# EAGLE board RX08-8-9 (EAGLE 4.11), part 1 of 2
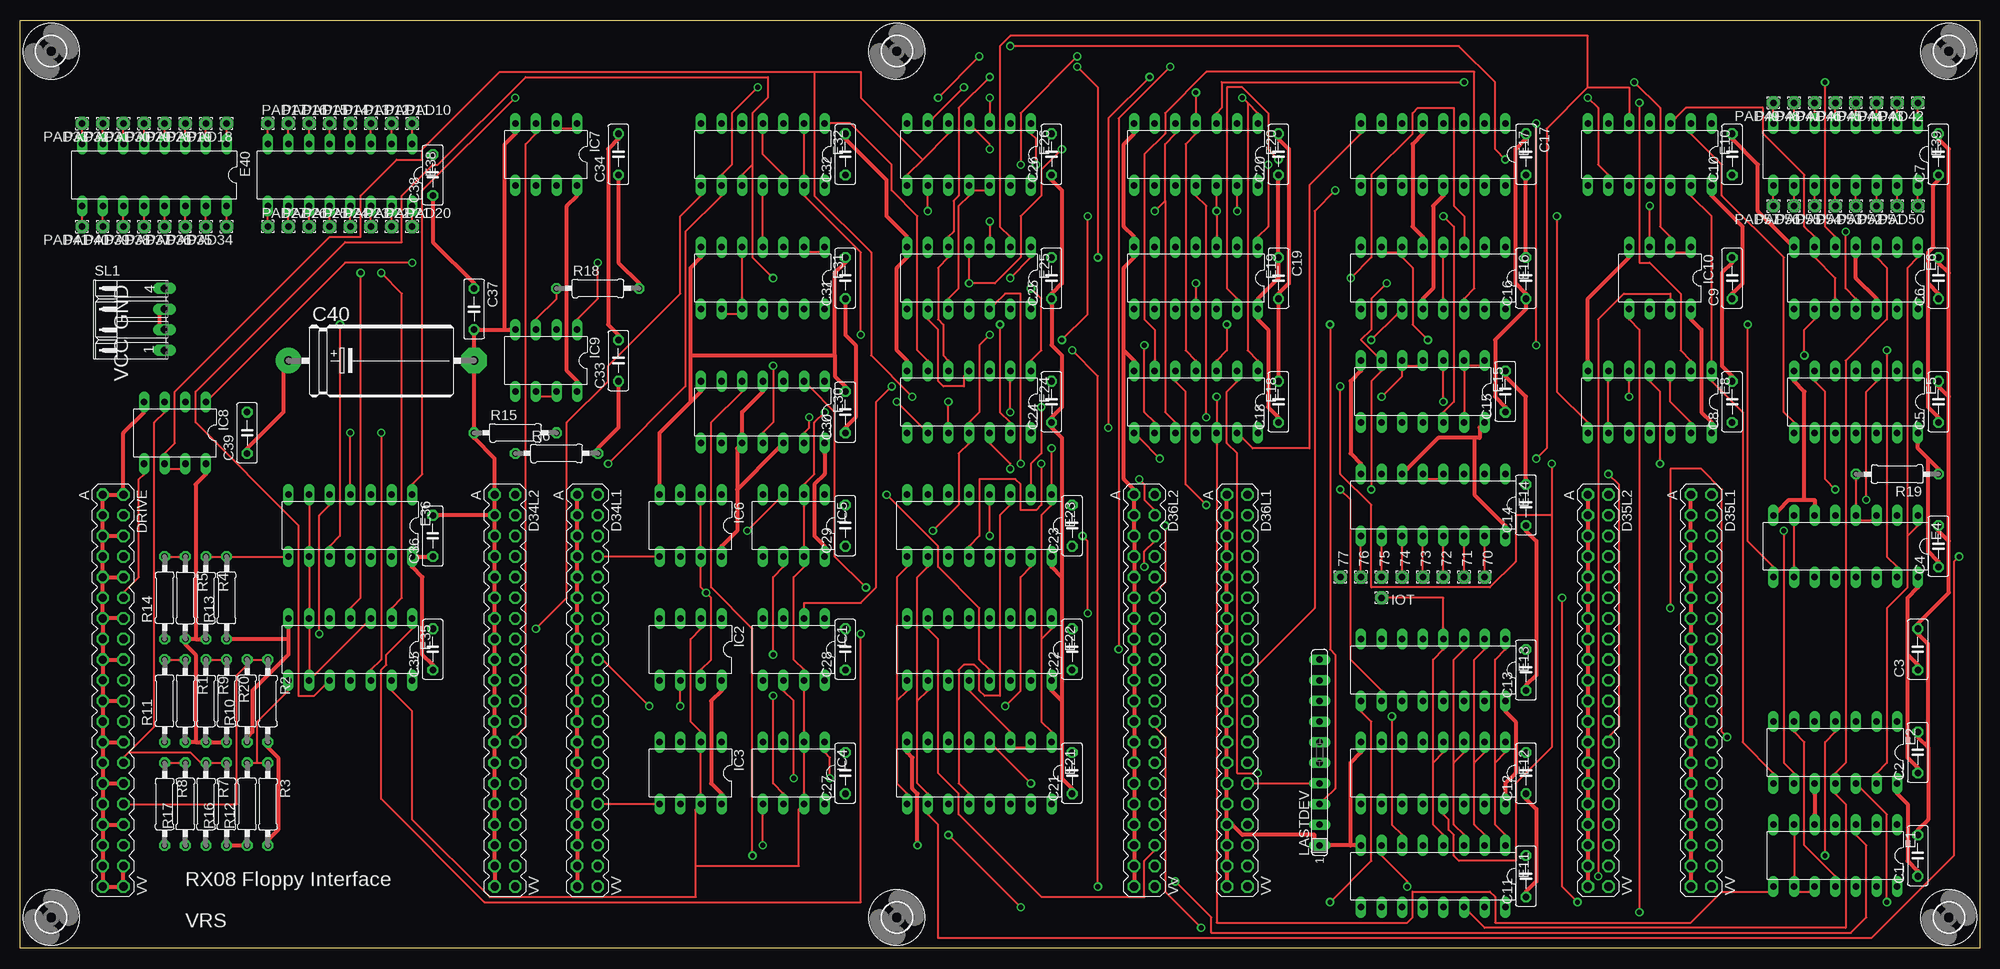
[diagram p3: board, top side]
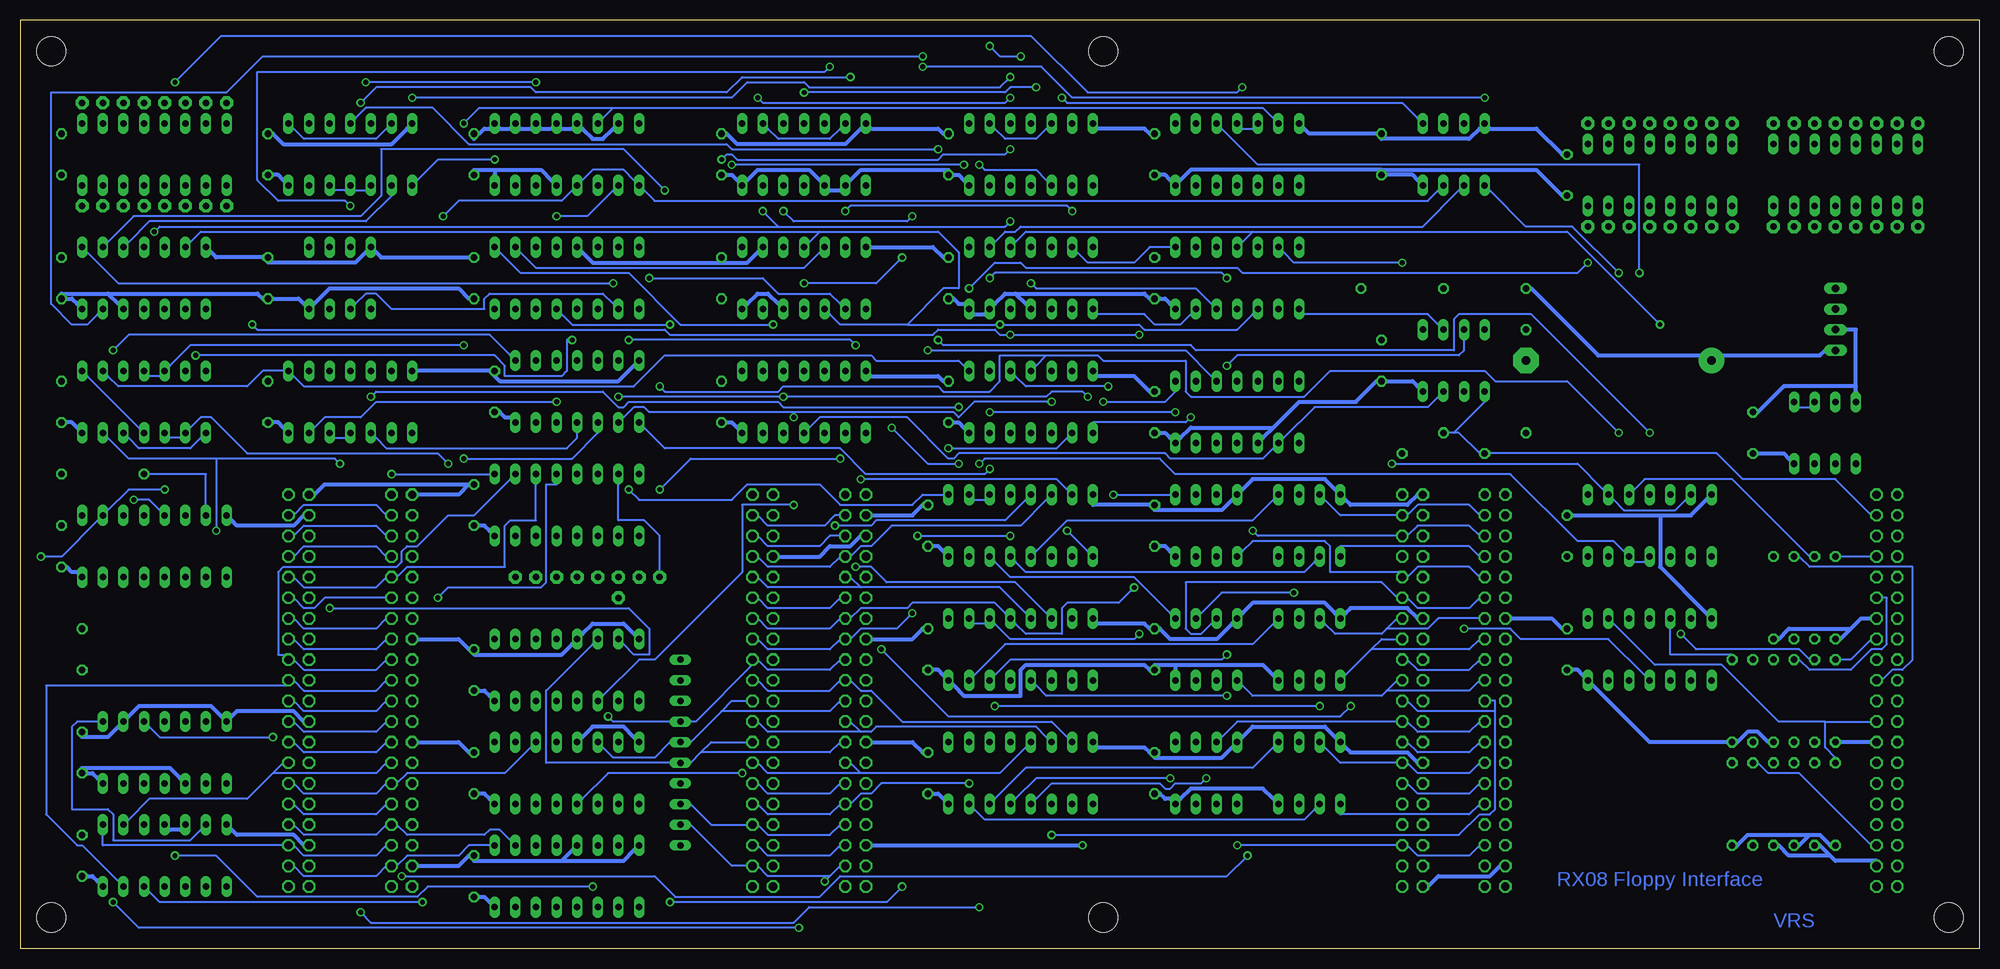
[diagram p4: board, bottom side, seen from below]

Size 241.3 x 114.3 mm. Coordinates in mm from the lower left corner, seen from the top.
Outline: 0,0 0,114.3 241.3,114.3 241.3,0 0,0
Copper layers (1*16): Top 0.035mm / dielectric 1.5mm / Bottom 0.035mm
Design rules "olimex10mil": minimum track width 10mil, minimum drill 24mil, track to track 10mil, track to pad 10mil, pad to pad 10mil, via to via 10mil, smd to smd 10mil, copper to edge 25mil, drill to drill 10mil, minimum pad ring 10mil, minimum via ring 8mil, stop-mask expansion 0mil, vias tented up to drill 0mil, thermal gap 10mil
Net classes: 1 supply: width 0.508 mm

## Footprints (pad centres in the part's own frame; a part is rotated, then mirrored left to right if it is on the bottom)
1,6/0,8 = drill 0.813 pad 1.6 octagon: 1 0,0
C050-025X075 = drill 0.813 octagon: 1 -2.54,0; 2 2.54,0
E22-9 = drill 1.016 pad 3.15 round: + -11.43,0 | drill 1.016 pad 3.15 octagon: - 11.43,0
DEC40PIN = drill 1.016 octagon: A -24.13,-1.27; AA 3.81,-1.27; B -24.13,1.27; BB 3.81,1.27; C -21.59,-1.27; CC 6.35,-1.27; D -21.59,1.27; DD 6.35,1.27; E -19.05,-1.27; EE 8.89,-1.27; F -19.05,1.27; FF 8.89,1.27; H -16.51,-1.27; HH 11.43,-1.27; J -16.51,1.27; JJ 11.43,1.27; K -13.97,-1.27; KK 13.97,-1.27; L -13.97,1.27; LL 13.97,1.27; M -11.43,-1.27; MM 16.51,-1.27; N -11.43,1.27; NN 16.51,1.27; P -8.89,-1.27; PP 19.05,-1.27; R -8.89,1.27; RR 19.05,1.27; S -6.35,-1.27; SS 21.59,-1.27; T -6.35,1.27; TT 21.59,1.27; U -3.81,-1.27; UU 24.13,-1.27; V -3.81,1.27; VV 24.13,1.27; W -1.27,-1.27; X -1.27,1.27; Y 1.27,-1.27; Z 1.27,1.27
DIL14 = drill 0.813 long: 1 -7.62,-3.81; 2 -5.08,-3.81; 3 -2.54,-3.81; 4 0,-3.81; 5 2.54,-3.81; 6 5.08,-3.81; 7 7.62,-3.81; 8 7.62,3.81; 9 5.08,3.81; 10 2.54,3.81; 11 0,3.81; 12 -2.54,3.81; 13 -5.08,3.81; 14 -7.62,3.81
DIL16 = drill 0.813 long: 1 -8.89,-3.81; 2 -6.35,-3.81; 3 -3.81,-3.81; 4 -1.27,-3.81; 5 1.27,-3.81; 6 3.81,-3.81; 7 6.35,-3.81; 8 8.89,-3.81; 9 8.89,3.81; 10 6.35,3.81; 11 3.81,3.81; 12 1.27,3.81; 13 -1.27,3.81; 14 -3.81,3.81; 15 -6.35,3.81; 16 -8.89,3.81
DIL08 = drill 0.813 long: 1 -3.81,-3.81; 2 -1.27,-3.81; 3 1.27,-3.81; 4 3.81,-3.81; 5 3.81,3.81; 6 1.27,3.81; 7 -1.27,3.81; 8 -3.81,3.81
SIL10 = drill 0.813 long: 1 -11.43,0; 2 -8.89,0; 3 -6.35,0; 4 -3.81,0; 5 -1.27,0; 6 1.27,0; 7 3.81,0; 8 6.35,0; 9 8.89,0; 10 11.43,0
0207/10 = drill 0.813 octagon: 1 -5.08,0; 2 5.08,0
04PA = drill 0.914 long: 1 -3.81,0; 2 -1.27,0; 3 1.27,0; 4 3.81,0
3,6 = hole 3.6: 0,0

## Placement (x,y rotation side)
70  [1,6/0,8]  180.34,45.72 270 top
71  [1,6/0,8]  177.8,45.72 270 top
72  [1,6/0,8]  175.26,45.72 270 top
73  [1,6/0,8]  172.72,45.72 270 top
74  [1,6/0,8]  170.18,45.72 270 top
75  [1,6/0,8]  167.64,45.72 270 top
76  [1,6/0,8]  165.1,45.72 270 top
77  [1,6/0,8]  162.56,45.72 270 top
C1  0.1  [C050-025X075]  233.68,11.43 90 top
C2  0.1  [C050-025X075]  233.68,24.13 90 top
C3  0.1  [C050-025X075]  233.68,36.83 90 top
C4  0.1  [C050-025X075]  236.22,49.53 90 top
C5  0.1  [C050-025X075]  236.22,67.31 90 top
C6  0.1  [C050-025X075]  236.22,82.55 90 top
C7  0.1  [C050-025X075]  236.22,97.79 90 top
C8  0.1  [C050-025X075]  210.82,67.31 90 top
C9  0.1  [C050-025X075]  210.82,82.55 90 top
C10  0.1  [C050-025X075]  210.82,97.79 90 top
C11  0.1  [C050-025X075]  185.42,8.89 90 top
C12  0.1  [C050-025X075]  185.42,21.59 90 top
C13  0.1  [C050-025X075]  185.42,34.29 90 top
C14  0.1  [C050-025X075]  185.42,54.61 90 top
C15  0.1  [C050-025X075]  182.88,68.58 90 top
C16  0.1  [C050-025X075]  185.42,82.55 90 top
C17  0.1  [C050-025X075]  185.42,97.79 270 top
C18  0.1  [C050-025X075]  154.94,67.31 90 top
C19  0.1  [C050-025X075]  154.94,82.55 270 top
C20  0.1  [C050-025X075]  154.94,97.79 90 top
C21  0.1  [C050-025X075]  129.54,21.59 90 top
C22  0.1  [C050-025X075]  129.54,36.83 90 top
C23  0.1  [C050-025X075]  129.54,52.07 90 top
C24  0.1  [C050-025X075]  127,67.31 90 top
C25  0.1  [C050-025X075]  127,82.55 90 top
C26  0.1  [C050-025X075]  127,97.79 90 top
C27  0.1  [C050-025X075]  101.6,21.59 90 top
C28  0.1  [C050-025X075]  101.6,36.83 90 top
C29  0.1  [C050-025X075]  101.6,52.07 90 top
C30  0.1  [C050-025X075]  101.6,66.04 90 top
C31  0.1  [C050-025X075]  101.6,82.55 90 top
C32  0.1  [C050-025X075]  101.6,97.79 90 top
C33  0.1  [C050-025X075]  73.66,72.39 90 top
C34  0.1  [C050-025X075]  73.66,97.79 90 top
C35  0.1  [C050-025X075]  50.8,36.83 90 top
C36  0.1  [C050-025X075]  50.8,50.8 90 top
C37  0.1  [C050-025X075]  55.88,78.74 270 top
C38  0.1  [C050-025X075]  50.8,95.25 90 top
C39  0.1  [C050-025X075]  27.94,63.5 90 top
C40  100uf  [E22-9]  44.45,72.39 0 top
D34L1  [DEC40PIN]  69.85,31.75 270 top
D34L2  [DEC40PIN]  59.69,31.75 270 top
D35L1  [DEC40PIN]  207.01,31.75 270 top
D35L2  [DEC40PIN]  194.31,31.75 270 top
D36L1  [DEC40PIN]  149.86,31.75 270 top
D36L2  [DEC40PIN]  138.43,31.75 270 top
DRIVE  [DEC40PIN]  11.43,31.75 270 top
E1  74LS10N  [DIL14]  223.52,11.43 180 top
E2  74LS74N  [DIL14]  223.52,24.13 180 top
E4  74LS161N  [DIL16]  224.79,49.53 180 top
E5  74LS00N  [DIL14]  226.06,67.31 180 top
E6  74LS74N  [DIL14]  226.06,82.55 180 top
E8  74LS10N  [DIL14]  200.66,67.31 180 top
E10  74LS10N  [DIL14]  200.66,97.79 180 top
E11  74LS138N  [DIL16]  173.99,8.89 180 top
E12  74LS138N  [DIL16]  173.99,21.59 180 top
E13  74LS138N  [DIL16]  173.99,34.29 180 top
E14  74LS138N  [DIL16]  173.99,54.61 180 top
E15  74LS00N  [DIL14]  172.72,68.58 180 top
E16  74LS75N  [DIL16]  173.99,82.55 180 top
E17  74LS76N  [DIL16]  173.99,97.79 180 top
E18  74LS02N  [DIL14]  144.78,67.31 180 top
E19  74LS74N  [DIL14]  144.78,82.55 180 top
E20  74HCT32N  [DIL14]  144.78,97.79 180 top
E21  74LS195N  [DIL16]  118.11,21.59 180 top
E22  74LS195N  [DIL16]  118.11,36.83 180 top
E23  74LS195N  [DIL16]  118.11,52.07 180 top
E24  74LS08N  [DIL14]  116.84,67.31 180 top
E25  74LS04N  [DIL14]  116.84,82.55 180 top
E26  74LS02N  [DIL14]  116.84,97.79 180 top
E30  74LS74N  [DIL14]  91.44,66.04 180 top
E31  74LS20N  [DIL14]  91.44,82.55 180 top
E32  74LS27N  [DIL14]  91.44,97.79 180 top
E35  74HCT02N  [DIL14]  40.64,36.83 180 top
E36  74HCT02N  [DIL14]  40.64,52.07 180 top
E38  SPARE  [DIL16]  39.37,95.25 180 top
E39  SPARE  [DIL16]  224.79,97.79 180 top
E40  SPARE  [DIL16]  16.51,95.25 180 top
IC1  DS75452N  [DIL08]  95.25,36.83 180 top
IC2  DS75452N  [DIL08]  82.55,36.83 180 top
IC3  DS75452N  [DIL08]  82.55,21.59 180 top
IC4  DS75452N  [DIL08]  95.25,21.59 180 top
IC5  DS75452N  [DIL08]  95.25,52.07 180 top
IC6  DS75452N  [DIL08]  82.55,52.07 180 top
IC7  DS75452N  [DIL08]  64.77,97.79 180 top
IC8  DS75452N  [DIL08]  19.05,63.5 180 top
IC9  DS75452N  [DIL08]  64.77,72.39 180 top
IC10  DS75452N  [DIL08]  201.93,82.55 180 top
IOT  [1,6/0,8]  167.64,43.18 270 top
LASTDEV  100  [SIL10]  160.02,24.13 90 top
PAD10  [1,6/0,8]  48.26,101.6 0 top
PAD11  [1,6/0,8]  45.72,101.6 0 top
PAD12  [1,6/0,8]  43.18,101.6 0 top
PAD13  [1,6/0,8]  40.64,101.6 0 top
PAD14  [1,6/0,8]  38.1,101.6 0 top
PAD15  [1,6/0,8]  35.56,101.6 0 top
PAD16  [1,6/0,8]  33.02,101.6 0 top
PAD17  [1,6/0,8]  30.48,101.6 0 top
PAD18  [1,6/0,8]  25.4,101.6 180 top
PAD19  [1,6/0,8]  22.86,101.6 180 top
PAD20  [1,6/0,8]  48.26,88.9 0 top
PAD21  [1,6/0,8]  45.72,88.9 0 top
PAD22  [1,6/0,8]  43.18,88.9 0 top
PAD23  [1,6/0,8]  40.64,88.9 0 top
PAD24  [1,6/0,8]  38.1,88.9 0 top
PAD25  [1,6/0,8]  35.56,88.9 0 top
PAD26  [1,6/0,8]  33.02,88.9 0 top
PAD27  [1,6/0,8]  30.48,88.9 0 top
PAD28  [1,6/0,8]  20.32,101.6 180 top
PAD29  [1,6/0,8]  17.78,101.6 180 top
PAD30  [1,6/0,8]  15.24,101.6 180 top
PAD31  [1,6/0,8]  12.7,101.6 180 top
PAD32  [1,6/0,8]  10.16,101.6 180 top
PAD33  [1,6/0,8]  7.62,101.6 180 top
PAD34  [1,6/0,8]  25.4,88.9 180 top
PAD35  [1,6/0,8]  22.86,88.9 180 top
PAD36  [1,6/0,8]  20.32,88.9 180 top
PAD37  [1,6/0,8]  17.78,88.9 180 top
PAD38  [1,6/0,8]  15.24,88.9 180 top
PAD39  [1,6/0,8]  12.7,88.9 180 top
PAD40  [1,6/0,8]  10.16,88.9 180 top
PAD41  [1,6/0,8]  7.62,88.9 180 top
PAD42  [1,6/0,8]  233.68,104.14 180 top
PAD43  [1,6/0,8]  231.14,104.14 180 top
PAD44  [1,6/0,8]  228.6,104.14 180 top
PAD45  [1,6/0,8]  226.06,104.14 180 top
PAD46  [1,6/0,8]  223.52,104.14 180 top
PAD47  [1,6/0,8]  220.98,104.14 180 top
PAD48  [1,6/0,8]  218.44,104.14 180 top
PAD49  [1,6/0,8]  215.9,104.14 180 top
PAD50  [1,6/0,8]  233.68,91.44 180 top
PAD51  [1,6/0,8]  231.14,91.44 180 top
PAD52  [1,6/0,8]  228.6,91.44 180 top
PAD53  [1,6/0,8]  226.06,91.44 180 top
PAD54  [1,6/0,8]  223.52,91.44 180 top
PAD55  [1,6/0,8]  220.98,91.44 180 top
PAD56  [1,6/0,8]  218.44,91.44 180 top
PAD57  [1,6/0,8]  215.9,91.44 180 top
R1  180  [0207/10]  20.32,30.48 270 top
R2  180  [0207/10]  30.48,30.48 270 top
R3  180  [0207/10]  30.48,17.78 270 top
R4  180  [0207/10]  22.86,43.18 270 top
R5  180  [0207/10]  20.32,43.18 270 top
R6  180  [0207/10]  66.04,60.96 0 top
R7  180  [0207/10]  22.86,17.78 270 top
R8  180  [0207/10]  17.78,17.78 270 top
R9  390  [0207/10]  22.86,30.48 270 top
R10  390  [0207/10]  27.94,30.48 90 top
R11  390  [0207/10]  17.78,30.48 90 top
R12  390  [0207/10]  27.94,17.78 90 top
R13  390  [0207/10]  25.4,43.18 90 top
R14  390  [0207/10]  17.78,43.18 90 top
R15  390  [0207/10]  60.96,63.5 0 top
R16  390  [0207/10]  25.4,17.78 90 top
R17  390  [0207/10]  20.32,17.78 90 top
R18  10K  [0207/10]  71.12,81.28 0 top
R19  10K  [0207/10]  231.14,58.42 180 top
R20  180  [0207/10]  25.4,30.48 270 top
SL1  [04PA]  17.78,77.47 90 top
U$1  [3,6]  237.49,3.81 0 top
U$2  [3,6]  237.49,110.49 0 top
U$3  [3,6]  3.81,110.49 0 top
U$4  [3,6]  3.81,3.81 0 top
U$5  [3,6]  107.95,110.49 0 top
U$6  [3,6]  107.95,3.81 0 top

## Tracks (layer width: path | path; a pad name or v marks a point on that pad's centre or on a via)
8/12  (via drill 0.61)
  Top 0.254: v201.93,59.69 201.93,68.58 200.66,69.85 E8.4 | v217.17,51.44 217.17,22.86 218.44,21.59 E2.9
  Bottom 0.254: v201.93,59.69 202.56,60.33 217.17,60.33 | 217.17,60.33 227.97,60.33 230.5,62.87 E5.13 | 217.17,60.33 v217.17,51.44
8/12\  (via drill 0.61)
  Top 0.254: E2.8 215.9,21.59 212.09,25.4 212.09,66.04 208.28,69.85 E8.1 208.28,72.39 208.28,90.17 205.74,92.71 E10.13 | v48.26,84.45 40.01,84.45 23.5,67.94 IC8.1 | v124.46,81.28 125.73,80.01 125.73,73.66 124.46,72.39 E24.1
  Bottom 0.254: IC8.2 20.95,66.67 22.23,66.67 IC8.1 | E24.1 125.09,71.75 125.73,72.39 135.89,72.39 136.53,73.03 161.93,73.03 165.74,69.22 206.38,69.22 207.65,70.48 E8.1 208.91,71.12 211.46,71.12 213.36,69.22 229.24,69.22 230.5,70.48 E5.2 | v48.26,84.45 49.53,83.19 90.81,83.19 91.44,83.82 117.47,83.82 118.11,84.45 121.28,84.45 v124.46,81.28
ACB00\
  Bottom 0.254: IC6.3 80.64,55.24 78.74,53.34 71.75,53.34 D34L1.D 70.48,53.34 69.22,54.61 62.87,54.61 61.59,53.34 D34L2.D
ACB01\
  Top 0.254: IC6.5 78.11,48.26 71.75,48.26 D34L1.J
  Bottom 0.254: D34L2.J 61.59,48.26 62.87,49.53 78.74,49.53 IC6.5
ACB02\
  Bottom 0.254: IC1.3 94.61,40.01 95.89,38.73 97.16,38.73 97.79,39.37 97.79,45.09 73.66,45.09 71.75,43.18 D34L1.N 70.48,43.18 69.22,41.91 62.87,41.91 61.59,43.18 D34L2.N
ACB03\
  Bottom 0.254: 74.93,36.83 73.66,38.1 71.75,38.1 D34L1.T | 74.93,36.83 78.11,33.66 IC2.5 | 74.93,36.83 62.87,36.83 61.59,38.1 D34L2.T
ACB04\
  Bottom 0.254: 73.03,31.75 71.75,33.02 D34L1.X | 73.03,31.75 73.66,31.11 89.53,31.11 90.81,32.38 IC1.5 | 73.03,31.75 62.87,31.75 61.59,33.02 D34L2.X
ACB05\
  Bottom 0.254: IC4.3 93.34,26.04 91.44,27.94 71.75,27.94 D34L1.BB 70.48,27.94 69.22,26.67 62.87,26.67 61.59,27.94 D34L2.BB
ACB06\
  Bottom 0.254: IC3.3 80.64,24.77 78.74,22.86 71.75,22.86 D34L1.FF 70.48,22.86 69.22,21.59 62.87,21.59 61.59,22.86 D34L2.FF
ACB07\
  Top 0.254: IC3.5 78.11,17.78 71.75,17.78 D34L1.LL
  Bottom 0.254: D34L2.LL 61.59,17.78 62.87,16.51 78.74,16.51 IC3.5
ACB08\  (via drill 0.61)
  Top 0.254: v91.44,12.7 91.44,16.51 IC4.5
  Bottom 0.254: v91.44,12.7 71.75,12.7 D34L1.RR 70.48,12.7 69.22,11.43 62.87,11.43 61.59,12.7 D34L2.RR
ACB09\  (via drill 0.61)
  Top 0.254: v89.53,51.44 93.34,55.24 IC5.3
  Bottom 0.254: v89.53,51.44 88.9,50.8 71.75,50.8 D34L1.F 70.48,50.8 69.22,52.07 62.87,52.07 61.59,50.8 D34L2.F
ACB10\
  Bottom 0.254: IC5.5 90.81,48.9 89.53,50.16 80.64,50.16 80.01,49.53 80.01,46.35 71.12,46.35 D34L1.L 70.48,45.72 69.22,46.99 62.87,46.99 61.59,45.72 D34L2.L
ACB11\
  Bottom 0.254: 73.03,39.37 71.75,40.64 D34L1.R | 73.03,39.37 73.66,38.73 79.38,38.73 80.64,40.01 IC2.3 | 73.03,39.37 67.94,39.37 66.67,40.64 61.59,40.64 D34L2.R
ACCLEAR\
  Top 0.254: IC7.3 63.5,100.33 62.23,99.06 62.23,27.3 60.96,26.04 D34L2.DD
  Bottom 0.254: D34L1.DD 70.48,25.4 69.22,24.13 62.87,24.13 61.59,25.4 D34L2.DD
BAC00  (via drill 0.61)
  Top 0.254: v137.79,57.78 138.43,57.15 138.43,55.24 139.7,53.98 D36L2.D
  Bottom 0.254: v137.79,57.78 113.67,57.78 112.39,56.52 E23.7 | D36L1.D 150.5,53.34 149.22,52.07 142.24,52.07 140.97,53.34 140.34,53.34 D36L2.D
BAC01
  Bottom 0.254: E23.6 114.94,55.24 118.11,52.07 133.99,52.07 136.53,49.53 137.79,49.53 139.06,48.26 D36L2.J 140.34,48.26 141.6,46.99 149.22,46.99 150.5,48.26 D36L1.J
BAC02  (via drill 0.61)
  Top 0.254: v140.97,52.07 140.97,45.09 139.7,43.81 D36L2.N
  Bottom 0.254: v140.97,52.07 136.53,52.07 135.89,52.7 120.02,52.7 117.47,55.24 E23.5 | D36L1.N 150.5,43.18 149.22,41.91 141.6,41.91 140.34,43.18 D36L2.N
BAC03  (via drill 0.61)
  Top 0.254: v119.38,50.8 119.38,54.61 E23.4 | v130.81,50.8 131.44,50.16 v131.44,41.27
  Bottom 0.254: v130.81,50.8 v119.38,50.8 | v131.44,41.27 133.35,39.37 137.79,39.37 139.06,38.1 D36L2.T 140.34,38.1 141.6,36.83 149.22,36.83 150.5,38.1 D36L1.T
BAC04  (via drill 0.61)
  Top 0.254: v161.93,93.34 159.38,90.81 159.38,41.91 151.13,33.66 D36L1.X
  Bottom 0.254: E21.7 112.39,26.04 114.3,27.94 132.72,27.94 136.53,31.75 137.79,31.75 139.06,33.02 D36L2.X 140.34,33.02 141.6,31.75 149.22,31.75 150.5,33.02 D36L1.X | v161.93,93.34 167,98.42 196.85,98.42 196.85,92.71 199.39,90.17 227.33,90.17 230.5,87 E6.2
BAC05  (via drill 0.61)
  Top 0.254: v229.87,5.71 229.87,16.51 226.69,19.68 E2.12 | v145.41,2.54 140.97,6.99 140.97,26.04 139.7,27.3 D36L2.BB
  Bottom 0.254: 137.79,26.67 136.53,26.67 135.89,27.3 116.2,27.3 114.94,26.04 E21.6 | 137.79,26.67 139.06,27.94 D36L2.BB | v229.87,5.71 226.69,2.54 v145.41,2.54 | 137.79,26.67 149.22,26.67 150.5,27.94 D36L1.BB
BAC06
  Bottom 0.254: 137.79,21.59 120.65,21.59 117.47,24.77 E21.5 | 137.79,21.59 139.06,22.86 D36L2.FF | 137.79,21.59 149.22,21.59 150.5,22.86 D36L1.FF
BAC07  (via drill 0.61)
  Top 0.254: v124.46,20.32 120.02,24.77 E21.4
  Bottom 0.254: v124.46,20.32 135.25,20.32 136.53,19.05 137.79,19.05 139.06,17.78 D36L2.LL 140.34,17.78 141.6,16.51 149.22,16.51 150.5,17.78 D36L1.LL
BAC08
  Top 0.254: E22.7 111.76,39.37 113.03,38.1 113.03,21.59 115.57,19.05 115.57,16.51 125.73,6.35 138.43,6.35 138.43,10.79 139.7,12.06 D36L2.RR
  Bottom 0.254: D36L1.RR 150.5,12.7 149.22,11.43 141.6,11.43 140.34,12.7 D36L2.RR
BAC09  (via drill 0.61)
  Top 0.254: v138.43,46.99 138.43,48.9 139.7,50.16 D36L2.F
  Bottom 0.254: v138.43,46.99 136.53,46.99 134.62,45.09 118.75,45.09 114.94,41.27 E22.6 | D36L1.F 150.5,50.8 149.22,49.53 142.88,49.53 141.6,50.8 140.34,50.8 D36L2.F
BAC10
  Bottom 0.254: 137.79,44.45 120.65,44.45 117.47,41.27 E22.5 | 137.79,44.45 139.06,45.72 D36L2.L | 137.79,44.45 149.22,44.45 150.5,45.72 D36L1.L
BAC11  (via drill 0.61)
  Top 0.254: v104.14,44.45 100.33,48.26 100.33,66.04 97.16,69.22 E30.2
  Bottom 0.254: D36L1.R 150.5,40.64 149.22,39.37 141.6,39.37 140.34,40.64 D36L2.R 139.06,40.64 137.79,41.91 132.08,41.91 131.44,42.55 121.28,42.55 120.02,41.27 E22.4 118.75,40.01 117.47,38.73 113.03,38.73 113.03,41.91 112.39,42.55 106.05,42.55 v104.14,44.45
BINIT  (via drill 0.61)
  Top 0.254: v142.24,8.26 146.69,3.81 146.69,1.91 225.43,1.91 227.33,3.81 227.33,12.7 226.06,13.97 E1.3
  Bottom 0.254: LASTDEV.2 158.75,15.24 153.67,10.16 151.76,10.16 D36L1.TT 150.5,10.16 149.22,8.89 141.6,8.89 | 141.6,8.89 140.34,10.16 D36L2.TT | v142.24,8.26 141.6,8.89
BIOP1  (via drill 0.61)
  Top 0.254: v168.91,28.57 168.91,15.24 170.18,13.97 E11.6
  Bottom 0.254: D36L2.V 140.34,35.56 141.6,34.29 149.22,34.29 150.5,35.56 D36L1.V 151.13,34.92 158.12,27.94 158.75,27.94 LASTDEV.7 161.29,27.94 168.28,27.94 v168.91,28.57
BIOP2
  Bottom 0.254: 154.94,29.21 153.67,30.48 151.76,30.48 D36L1.Z | 154.94,29.21 158.75,25.4 LASTDEV.6 161.29,25.4 163.19,23.5 168.28,23.5 169.54,24.77 E12.6 | 154.94,29.21 141.6,29.21 140.34,30.48 D36L2.Z
BIOP4
  Bottom 0.254: 157.48,24.13 156.21,25.4 151.76,25.4 D36L1.DD | 157.48,24.13 158.75,22.86 LASTDEV.5 161.29,22.86 176.53,22.86 176.53,31.75 170.81,37.47 E13.6 | 157.48,24.13 141.6,24.13 140.34,25.4 D36L2.DD
BMB00
  Bottom 0.254: D35L2.D 196.22,53.34 197.49,54.61 206.38,54.61 207.65,53.34 D35L1.D
BMB01
  Bottom 0.254: D35L2.J 196.22,48.26 197.49,49.53 206.38,49.53 207.65,48.26 D35L1.J
BMB02
  Bottom 0.254: D35L2.N 196.22,43.18 203.84,43.18 205.1,41.91 206.38,41.91 207.65,43.18 D35L1.N
BMB03
  Bottom 0.254: E1.13 229.24,8.26 233.68,12.7 234.31,12.7 238.12,16.51 238.12,32.38 208.28,32.38 D35L1.X 207.65,33.02 206.38,31.75 197.49,31.75 196.22,33.02 D35L2.X
BMB03\
  Bottom 0.254: D35L2.T 196.22,38.1 197.49,36.83 206.38,36.83 207.65,38.1 D35L1.T
BMB04
  Bottom 0.254: 210.19,21.59 208.91,22.86 D35L1.FF | 210.19,21.59 213.36,18.41 225.43,18.41 227.97,15.88 E1.2 | 210.19,21.59 197.49,21.59 196.22,22.86 D35L2.FF
BMB04\
  Bottom 0.254: D35L2.BB 196.22,27.94 197.49,26.67 206.38,26.67 207.65,27.94 D35L1.BB
BMB05
  Bottom 0.254: E1.1 231.14,13.97 231.14,12.7 208.91,12.7 D35L1.RR 207.65,12.7 206.38,11.43 197.49,11.43 196.22,12.7 D35L2.RR
BMB05\
  Bottom 0.254: D35L2.LL 196.22,17.78 197.49,16.51 206.38,16.51 207.65,17.78 D35L1.LL
BMB06
  Bottom 0.254: E14.3 177.8,57.15 177.8,52.7 180.97,52.7 181.61,52.07 181.61,46.99 193.68,46.99 194.94,45.72 D35L2.L 196.22,45.72 197.49,44.45 206.38,44.45 207.65,45.72 D35L1.L
BMB06\
  Bottom 0.254: D35L2.F 196.22,50.8 197.49,52.07 206.38,52.07 207.65,50.8 D35L1.F
BMB07
  Bottom 0.254: E14.2 180.97,57.78 185.42,53.34 188.59,53.34 192.41,49.53 193.68,49.53 194.31,48.9 194.31,47.62 194.94,46.99 208.91,46.99 209.55,46.35 209.55,36.2 208.28,36.2 D35L1.V 207.65,35.56 206.38,34.29 197.49,34.29 196.22,35.56 D35L2.V
BMB07\
  Bottom 0.254: D35L2.R 196.22,40.64 197.49,39.37 206.38,39.37 207.65,40.64 D35L1.R
BMB08  (via drill 0.61)
  Top 0.254: v195.58,58.42 196.85,57.15 196.85,27.3 195.58,26.04 D35L2.DD
  Bottom 0.254: v195.58,58.42 183.51,58.42 E14.1 | D35L1.DD 207.65,25.4 206.38,24.13 197.49,24.13 196.22,25.4 D35L2.DD
BMB08\
  Bottom 0.254: D35L2.Z 196.22,30.48 197.49,29.21 206.38,29.21 207.65,30.48 D35L1.Z
BMB09
  Top 0.254: 176.53,22.86 176.53,15.24 177.8,13.97 E11.3 | 176.53,22.86 177.8,24.13 E12.3 | 176.53,22.86 176.53,35.56 177.8,36.83 E13.3
  Bottom 0.254: D35L1.JJ 207.65,20.32 206.38,19.05 197.49,19.05 196.22,20.32 D35L2.JJ 194.94,20.32 193.68,21.59 181.61,21.59 178.44,24.77 E12.3
BMB10
  Top 0.254: 179.07,22.86 179.07,15.24 180.34,13.97 E11.2 | 179.07,22.86 180.34,24.13 E12.2 | 179.07,22.86 179.07,35.56 180.34,36.83 E13.2
  Bottom 0.254: D35L1.NN 207.65,15.24 206.38,13.97 197.49,13.97 196.22,15.24 D35L2.NN 194.94,15.24 193.68,13.97 184.15,13.97 183.51,14.61 182.25,14.61 180.97,13.34 E11.2
BMB11
  Top 0.254: 181.61,22.86 181.61,15.24 182.88,13.97 E11.1 | 181.61,22.86 182.88,24.13 E12.1 | 181.61,22.86 181.61,35.56 182.88,36.83 E13.1
  Bottom 0.254: D35L1.TT 207.65,10.16 206.38,8.89 197.49,8.89 196.22,10.16 D35L2.TT 194.94,10.16 193.68,11.43 187.32,11.43 186.06,12.7 183.51,12.7 E11.1
BRUN\
  Bottom 0.254: D34L2.JJ 61.59,20.32 62.87,19.05 69.22,19.05 70.48,20.32 D34L1.JJ
BTS1  (via drill 0.61)
  Top 0.254: E16.13 175.26,80.01 175.26,85.09 E16.4 | v161.29,76.83 161.29,36.83 161.93,36.2 161.93,19.68 160.66,18.41 LASTDEV.3
  Bottom 0.254: LASTDEV.3 158.75,17.78 156.21,15.24 151.76,15.24 D36L1.NN 150.5,15.24 149.22,13.97 141.6,13.97 140.34,15.24 D36L2.NN | v161.29,76.83 173.35,76.83 174.62,78.11 E16.13
BTS3
  Top 0.254: LASTDEV.4 158.75,20.32 151.76,20.32 D36L1.JJ
  Bottom 0.254: D36L2.JJ 140.34,20.32 141.6,19.05 149.22,19.05 150.5,20.32 D36L1.JJ
CLK_BUF  (via drill 0.61)
  Top 0.254: v223.52,56.52 222.25,57.78 222.25,68.58 220.98,69.85 E5.6 | 110.49,30.48 110.49,20.32 111.76,19.05 E21.10 111.76,16.51 113.03,15.24 113.03,1.27 227.97,1.27 238.12,11.43 238.12,47.62 v238.76,48.26 | 110.49,30.48 111.76,31.75 E22.10 | 110.49,30.48 110.49,45.72 111.76,46.99 E23.10
  Bottom 0.254: v223.52,56.52 227.97,56.52 230.5,53.98 E4.2 231.78,52.7 236.22,48.26 v238.76,48.26
CLK_PARITY\  (via drill 0.61)
  Top 0.254: v186.69,74.3 v186.69,101.6
  Bottom 0.254: E5.4 225.43,70.48 224.16,70.48 E5.5 222.88,71.75 220.34,74.3 v186.69,74.3 | 168.28,103.5 88.27,103.5 87,102.23 E32.6 | 168.28,103.5 169.54,102.23 E17.6 | v186.69,101.6 184.78,103.5 168.28,103.5
DONE  (via drill 0.61)
  Top 0.254: v39.37,76.83 39.37,50.8 38.1,49.53 E36.10 | E32.11 91.44,92.71 91.44,87.63 E31.4 | v149.86,90.81 149.86,92.71 E20.13 | v119.38,89.53 119.38,87.63 E25.3 | v224.79,88.27 224.79,81.28 226.06,80.01 E6.11
  Bottom 0.254: v39.37,76.83 50.8,88.27 89.53,88.27 | 89.53,88.27 90.81,87 E31.4 | 89.53,88.27 117.47,88.27 118.75,87 E25.3 | 147.96,88.9 v149.86,90.81 | 147.96,88.9 120.02,88.9 v119.38,89.53 | v224.79,88.27 224.16,88.9 147.96,88.9
DONE\  (via drill 0.61)
  Top 0.254: E25.4 116.84,85.09 v116.84,81.92 120.02,81.92 123.19,85.09 123.19,90.17 125.73,92.71 125.73,95.89 v128.27,98.42
  Bottom 0.254: v116.84,81.92 116.2,81.28 96.52,81.28 94.61,79.38 E31.12 | v128.27,98.42 153.67,98.42 154.31,99.06 186.06,99.06 190.5,103.5 198.75,103.5 200.03,102.23 E10.4
DONE_FF
  Bottom 0.254: E16.10 168.28,79.38 169.54,80.64 183.51,80.64 184.15,80.01 184.15,78.74 195.58,78.74 197.49,80.64 198.75,80.64 200.03,79.38 IC10.6
DONE_SKIP  (via drill 0.61)
  Top 0.254: v111.76,90.81 111.76,92.71 E26.9 | v139.7,90.81 140.97,92.08 | 140.97,92.08 140.97,99.06 142.24,100.33 E20.5 | 140.97,92.08 140.97,66.04 142.24,64.77 E18.10
  Bottom 0.254: v111.76,90.81 112.39,91.44 139.06,91.44 v139.7,90.81
ENB_BUF_LD\  (via drill 0.61)
  Top 0.254: 107.95,30.48 107.95,20.32 109.22,19.05 E21.9 | 107.95,30.48 109.22,31.75 E22.9 | 107.95,30.48 107.95,45.72 109.22,46.99 E23.9 | E32.2 96.52,100.33 96.52,95.25 E32.13 96.52,92.71 103.5,85.72 v103.5,75.56 | v212.72,76.83 212.72,50.16 215.9,46.99 E4.9 | v119.38,75.56 118.11,74.3 118.11,66.04 116.84,64.77 E24.11 116.84,62.23 115.57,60.96 115.57,54.61 v112.39,51.44
  Bottom 0.254: v212.72,76.83 212.09,76.2 161.93,76.2 161.29,75.56 128.91,75.56 128.27,76.2 121.28,76.2 120.65,75.56 v119.38,75.56 v103.5,75.56 | v112.39,51.44 109.86,48.9 E23.9
ERR_SKIP  (via drill 0.61)
  Top 0.254: v116.2,106.05 112.39,102.23 E26.6 | v144.78,105.41 144.78,102.87 E20.4 144.78,100.33 143.51,99.06 143.51,73.66 144.78,72.39 E18.4
  Bottom 0.254: v116.2,106.05 119.38,106.05 120.02,105.41 v144.78,105.41
ERROR  (via drill 0.61)
  Top 0.254: v60.96,104.78 49.53,93.34 49.53,58.42 48.26,57.15 E36.1 | v130.18,108.58 132.72,106.05 v132.72,85.09 | v144.78,81.92 144.78,80.01 E19.11
  Bottom 0.254: v60.96,104.78 111.76,104.78 115.57,108.58 v130.18,108.58 | v132.72,85.09 135.89,81.92 v144.78,81.92
GND  (via drill 0.61)
  Top 0.508: D34L1.UU 68.58,8.26 68.58,9.53 D34L1.SS 68.58,10.79 68.58,12.06 D34L1.PP 68.58,13.34 68.58,14.61 D34L1.MM 68.58,15.88 68.58,17.14 D34L1.KK 68.58,18.41 68.58,19.68 D34L1.HH 68.58,20.95 68.58,22.23 D34L1.EE 68.58,23.5 68.58,24.77 D34L1.CC 68.58,26.04 68.58,27.3 D34L1.AA 68.58,28.57 68.58,29.84 D34L1.Y 68.58,31.11 68.58,32.38 D34L1.W 68.58,33.66 68.58,34.92 D34L1.U 68.58,36.2 68.58,37.47 D34L1.S 68.58,38.73 68.58,40.01 D34L1.P 68.58,41.27 68.58,42.55 D34L1.M 68.58,43.81 68.58,45.09 D34L1.K 68.58,46.35 68.58,47.62 D34L1.H 68.58,48.9 68.58,50.16 D34L1.E 68.58,51.44 68.58,52.7 D34L1.C 68.58,53.98 68.58,55.24 D34L1.A | 100.33,73.03 100.33,70.48 101.6,69.22 C30.2 | 100.33,73.03 100.33,83.19 101.6,84.45 C31.2 | E24.7 109.22,72.39 107.95,73.66 107.95,83.82 109.22,85.09 E25.7 109.22,87.63 106.68,90.17 106.68,94.61 101.6,99.69 C32.2 | 82.55,67.31 78.74,63.5 78.74,57.15 IC6.4 | 82.55,67.31 83.82,68.58 E30.7 | 82.55,67.31 82.55,73.03 | 82.55,73.03 82.55,83.82 83.82,85.09 E31.7 | 82.55,73.03 100.33,73.03 | SL1.3 17.14,78.11 17.14,76.83 SL1.2 | 33.02,38.1 33.02,39.37 E35.7 | 33.02,38.1 33.02,36.2 28.57,31.75 28.57,26.67 27.94,26.04 R10.1 | 33.02,38.1 26.04,38.1 R13.1 | R16.1 26.04,12.7 27.3,12.7 R12.1 | DRIVE.MM 10.16,14.61 10.16,13.34 DRIVE.PP 10.16,12.06 10.16,10.79 DRIVE.SS 10.16,9.53 10.16,8.26 DRIVE.UU 10.79,7.62 12.06,7.62 DRIVE.VV 12.7,8.26 12.7,9.53 DRIVE.TT | DRIVE.NN 12.06,15.24 10.79,15.24 DRIVE.MM | DRIVE.MM 10.16,15.88 10.16,17.14 DRIVE.KK 10.16,18.41 10.16,19.68 DRIVE.HH | DRIVE.JJ 12.06,20.32 10.79,20.32 DRIVE.HH | DRIVE.HH 10.16,20.95 10.16,22.23 DRIVE.EE 10.16,23.5 10.16,24.77 DRIVE.CC
  Top 0.508: DRIVE.CC 10.16,26.04 10.16,27.3 DRIVE.AA 10.16,28.57 10.16,29.84 DRIVE.Y | DRIVE.Z 12.06,30.48 10.79,30.48 DRIVE.Y | DRIVE.Y 10.16,31.11 10.16,32.38 DRIVE.W 10.16,33.66 10.16,34.92 DRIVE.U | DRIVE.V 12.06,35.56 10.79,35.56 DRIVE.U | DRIVE.U 10.16,36.2 10.16,37.47 DRIVE.S 10.16,38.73 10.16,40.01 DRIVE.P | DRIVE.P 10.16,41.27 10.16,42.55 DRIVE.M 10.16,43.81 10.16,45.09 DRIVE.K | DRIVE.L 12.06,45.72 10.79,45.72 DRIVE.K | DRIVE.K 10.16,46.35 10.16,47.62 DRIVE.H 10.16,48.9 10.16,50.16 DRIVE.E | DRIVE.F 12.06,50.8 10.79,50.8 DRIVE.E | DRIVE.E 10.16,51.44 10.16,52.7 DRIVE.C 10.16,53.98 10.16,55.24 DRIVE.A 10.79,55.88 12.06,55.88 DRIVE.B 12.7,56.52 12.7,63.5 15.24,66.04 IC8.4 | DRIVE.DD 12.06,25.4 10.79,25.4 DRIVE.CC | DRIVE.R 12.06,40.64 10.79,40.64 DRIVE.P | C33.2 73.66,75.56 72.39,76.83 72.39,98.42 73.66,99.69 C34.2 | D34L2.UU 58.42,8.26 58.42,9.53 D34L2.SS 58.42,10.79 58.42,12.06 D34L2.PP 58.42,13.34 58.42,14.61 D34L2.MM 58.42,15.88 58.42,17.14 D34L2.KK 58.42,18.41 58.42,19.68 D34L2.HH 58.42,20.95 58.42,22.23 D34L2.EE 58.42,23.5 58.42,24.77 D34L2.CC 58.42,26.04 58.42,27.3 D34L2.AA 58.42,28.57 58.42,29.84 D34L2.Y 58.42,31.11 58.42,32.38 D34L2.W 58.42,33.66 58.42,34.92 D34L2.U 58.42,36.2 58.42,37.47 D34L2.S 58.42,38.73 58.42,40.01 D34L2.P 58.42,41.27 58.42,42.55 D34L2.M 58.42,43.81 58.42,45.09 D34L2.K 58.42,46.35 58.42,47.62 D34L2.H 58.42,48.9 58.42,50.16 D34L2.E 58.42,51.44 58.42,52.7 D34L2.C | 59.69,76.2 56.52,76.2 C37.2 55.88,75.56 55.88,73.66 C40.- 55.88,71.12 55.88,64.14 R15.1 55.88,62.87 58.42,60.33 58.42,56.52 D34L2.A 58.42,55.24 58.42,53.98 D34L2.C
  Top 0.508: 59.69,76.2 60.33,76.2 IC9.4 | C36.2 51.44,53.34 57.78,53.34 D34L2.C | 59.69,76.2 59.69,99.06 60.96,100.33 IC7.4 | D36L2.UU 137.16,8.26 137.16,9.53 D36L2.SS 137.16,10.79 137.16,12.06 D36L2.PP 137.16,13.34 137.16,14.61 D36L2.MM 137.16,15.88 137.16,17.14 D36L2.KK 137.16,18.41 137.16,19.68 D36L2.HH 137.16,20.95 137.16,22.23 D36L2.EE 137.16,23.5 137.16,24.77 D36L2.CC 137.16,26.04 137.16,27.3 D36L2.AA 137.16,28.57 137.16,29.84 D36L2.Y 137.16,31.11 137.16,32.38 D36L2.W 137.16,33.66 137.16,34.92 D36L2.U 137.16,36.2 137.16,37.47 D36L2.S 137.16,38.73 137.16,40.01 D36L2.P 137.16,41.27 137.16,42.55 D36L2.M 137.16,43.81 137.16,45.09 D36L2.K 137.16,46.35 137.16,47.62 D36L2.H 137.16,48.9 137.16,50.16 D36L2.E 137.16,51.44 137.16,52.7 D36L2.C 137.16,53.98 137.16,55.24 D36L2.A 137.16,56.52 135.89,57.78 135.89,73.66 | 135.89,73.66 137.16,72.39 E18.7 | 135.89,73.66 135.89,83.82 137.16,85.09 E19.7 137.16,87.63 135.89,88.9 135.89,99.06 137.16,100.33 E20.7 | C18.2 154.94,70.48 154.94,79.38 C19.2 154.94,80.64 156.21,81.92 156.21,98.42 154.94,99.69 C20.2 | 234.95,24.77 234.95,15.88 233.68,14.61 C1.2 | 234.95,24.77 233.68,26.04 C2.2 | 234.95,24.77 234.95,37.47 233.68,38.73 C3.2 233.68,40.01 237.49,43.81 237.49,50.16 | 237.49,50.16 236.22,51.44 C4.2 | 237.49,67.94 236.22,69.22 C5.2 | 237.49,50.16 237.49,67.94 | 237.49,83.19 236.22,84.45 C6.2 | 237.49,67.94 237.49,83.19 | 237.49,83.19 237.49,98.42 236.22,99.69 C7.2 | D35L1.UU 205.74,8.26 205.74,9.53 D35L1.SS 205.74,10.79 205.74,12.06 D35L1.PP 205.74,13.34 205.74,14.61 D35L1.MM 205.74,15.88 205.74,17.14 D35L1.KK 205.74,18.41 205.74,19.68 D35L1.HH 205.74,20.95 205.74,22.23 D35L1.EE 205.74,23.5 205.74,24.77 D35L1.CC 205.74,26.04 205.74,27.3 D35L1.AA 205.74,28.57 205.74,29.84 D35L1.Y 205.74,31.11 205.74,32.38 D35L1.W 205.74,33.66 205.74,34.92 D35L1.U 205.74,36.2 205.74,37.47 D35L1.S 205.74,38.73 205.74,40.01 D35L1.P 205.74,41.27 205.74,42.55 D35L1.M 205.74,43.81 205.74,45.09 D35L1.K 205.74,46.35 205.74,47.62 D35L1.H 205.74,48.9 205.74,50.16 D35L1.E 205.74,51.44 205.74,52.7 D35L1.C 205.74,53.98 205.74,55.24 D35L1.A
  Top 0.508: 219.71,55.24 220.98,55.24 220.98,54.61 E4.6 | 219.71,55.24 217.81,55.24 216.53,53.98 E4.8 | 219.71,55.24 219.71,68.58 218.44,69.85 E5.7 | E16.12 172.72,80.01 173.99,81.28 173.99,91.44 175.26,92.71 E17.13 | C16.2 185.42,85.72 185.42,94.61 C17.2 | C8.2 210.82,70.48 209.55,71.75 209.55,83.19 210.82,84.45 C9.2 | C10.2 210.82,99.69 214,96.52 214,90.81 217.81,87 E6.7 | E14.8 165.1,59.69 163.83,60.96 163.83,69.85 165.1,71.12 E15.7 | D35L2.A 193.04,55.24 193.04,53.98 D35L2.C 193.04,52.7 193.04,51.44 D35L2.E 193.04,50.16 193.04,48.9 D35L2.H 193.04,47.62 193.04,46.35 D35L2.K 193.04,45.09 193.04,43.81 D35L2.M 193.04,42.55 193.04,41.27 D35L2.P 193.04,40.01 193.04,38.73 D35L2.S 193.04,37.47 193.04,36.2 D35L2.U 193.04,34.92 193.04,33.66 D35L2.W 193.04,32.38 193.04,31.11 D35L2.Y 193.04,29.84 193.04,28.57 D35L2.AA 193.04,27.3 193.04,26.04 D35L2.CC 193.04,24.77 193.04,23.5 D35L2.EE 193.04,22.23 193.04,20.95 D35L2.HH 193.04,19.68 193.04,18.41 D35L2.KK 193.04,17.14 193.04,15.88 D35L2.MM 193.04,14.61 193.04,13.34 D35L2.PP 193.04,12.06 193.04,10.79 D35L2.SS 193.04,9.53 193.04,8.26 D35L2.UU | C15.2 182.88,70.48 185.42,67.94 185.42,57.78 C14.2 | D36L1.UU 148.59,8.26 148.59,9.53 D36L1.SS 148.59,10.79 148.59,12.06 D36L1.PP 148.59,13.34 148.59,14.61 D36L1.MM | D36L1.MM 148.59,15.88 148.59,17.14 D36L1.KK 148.59,18.41 148.59,19.68 D36L1.HH 148.59,20.95 148.59,22.23 D36L1.EE 148.59,23.5 148.59,24.77 D36L1.CC 148.59,26.04 148.59,27.3 D36L1.AA 148.59,28.57 148.59,29.84 D36L1.Y 148.59,31.11 148.59,32.38 D36L1.W 148.59,33.66 148.59,34.92 D36L1.U 148.59,36.2 148.59,37.47 D36L1.S 148.59,38.73 148.59,40.01 D36L1.P 148.59,41.27 148.59,42.55 D36L1.M 148.59,43.81 148.59,45.09 D36L1.K 148.59,46.35 148.59,47.62 D36L1.H 148.59,48.9 148.59,50.16 D36L1.E 148.59,51.44 148.59,52.7 D36L1.C 148.59,53.98 148.59,55.24 D36L1.A
  Top 0.508: 163.83,12.7 164.47,12.7 E11.8 | 163.83,12.7 161.29,12.7 LASTDEV.1 159.38,13.34 159.38,13.97 150.5,13.97 149.22,15.24 D36L1.MM | 163.83,12.7 163.83,22.86 165.1,24.13 E12.8 | IC10.4 198.12,85.09 193.04,80.01 193.04,72.39 E8.7 | v110.49,12.7 110.49,19.05 109.86,19.68 109.86,23.5 109.22,24.13 E21.8
  Bottom 0.508: E21.8 108.58,24.77 102.87,24.77 102.23,24.13 C27.2 101.6,23.5 93.34,23.5 92.08,24.77 IC4.4 90.81,26.04 89.53,27.3 80.64,27.3 79.38,26.04 IC3.4 78.11,24.77 77.47,24.13 70.48,24.13 69.22,22.86 D34L1.EE | E22.8 108.58,40.01 102.87,40.01 102.23,39.37 C28.2 100.97,39.37 99.69,38.1 93.98,38.1 92.08,40.01 IC1.4 90.81,41.27 89.53,42.55 80.64,42.55 79.38,41.27 IC2.4 78.11,41.27 77.47,41.91 70.48,41.91 69.22,40.64 D34L1.P | C32.2 102.23,100.33 102.87,100.97 108.58,100.97 E26.7 | C30.2 102.23,68.58 104.14,70.48 108.58,70.48 E24.7 | E23.8 109.22,54.61 102.23,54.61 C29.2 101.6,53.98 93.34,53.98 92.08,55.24 IC5.4 90.81,56.52 89.53,57.78 80.64,57.78 79.38,56.52 IC6.4 78.11,55.24 77.47,54.61 70.48,54.61 69.22,55.88 D34L1.A | 15.24,69.22 15.24,76.2 16.51,76.2 SL1.2 | 15.24,69.22 15.24,68.58 IC8.4 | 15.24,69.22 24.13,69.22 27.3,66.04 C39.2 | 18.41,11.43 17.78,10.79 12.7,10.79 DRIVE.TT | 18.41,11.43 19.68,12.7 R17.1 | 18.41,11.43 23.5,11.43 24.77,12.7 R16.1 | 15.88,39.37 14.61,40.64 13.34,40.64 DRIVE.R | 15.88,39.37 17.14,38.1 R14.1 | R11.1 17.14,25.4 13.34,25.4 DRIVE.DD | 15.88,39.37 23.5,39.37 24.77,38.1 R13.1 | C38.2 51.44,97.79 54.61,100.97 60.33,100.97 IC7.4 61.59,100.97 62.87,99.69 73.66,99.69 C34.2 74.3,100.33 82.55,100.33 83.19,100.97 E32.7 | C35.2 51.44,39.37 52.7,40.64 57.78,40.64 D34L2.P | 39.37,53.34 50.16,53.34 C36.2 | 39.37,53.34 35.56,53.34 33.66,55.24 E36.7 | 39.37,53.34 39.37,46.99 33.66,41.27 E35.7 | D34L1.UU 67.94,7.62 66.67,8.89 60.33,8.89 59.05,10.16 D34L2.SS | C23.2 130.18,54.61 131.44,53.34 136.53,53.34 D36L2.C | C22.2 130.18,39.37 131.44,38.1 136.53,38.1 D36L2.S
  Bottom 0.508: C21.2 130.18,24.13 131.44,25.4 136.53,25.4 D36L2.CC | C24.2 127.64,69.85 128.27,70.48 136.53,70.48 E18.7 | C25.2 127.64,85.09 128.91,86.36 136.53,86.36 E19.7 | C26.2 127.64,100.33 128.27,100.97 136.53,100.97 E20.7 137.79,100.97 139.7,99.06 153.03,99.06 154.31,100.33 C20.2 | C2.2 233.68,26.04 230.5,26.04 229.24,27.3 E2.2 227.97,28.57 226.69,29.84 217.81,29.84 216.53,28.57 E2.7 215.26,28.57 214.63,29.21 207.65,29.21 206.38,27.94 D35L1.AA | E1.7 215.26,14.61 214.63,13.97 207.65,13.97 206.38,12.7 D35L1.PP | E4.8 215.26,52.7 214.63,52.07 207.65,52.07 206.38,53.34 D35L1.C | C16.2 186.06,85.09 196.85,85.09 197.49,85.72 IC10.4 198.75,85.72 200.03,84.45 210.82,84.45 C9.2 211.46,85.09 217.17,85.09 217.81,85.72 E6.7 | 182.88,95.89 185.42,95.89 C17.2 | 182.88,95.89 177.16,95.89 175.9,94.61 E17.13 | E10.7 193.68,100.97 195.58,99.06 208.91,99.06 210.19,100.33 C10.2 | C12.2 186.06,24.13 187.32,25.4 192.41,25.4 D35L2.CC | E8.7 192.41,71.12 183.51,71.12 C15.2 182.88,70.48 182.25,69.85 167.64,69.85 165.74,71.75 E15.7 | 186.06,57.15 187.32,55.88 192.41,55.88 D35L2.A | 186.06,57.15 C14.2 186.06,57.15 | E13.8 165.74,38.73 167,40.01 170.81,40.01 172.09,38.73 E13.5 173.35,37.47 174.62,36.2 185.42,36.2 C13.2 186.06,36.83 187.32,38.1 192.41,38.1 D35L2.S | E12.5 172.09,26.04 170.81,27.3 167,27.3 165.74,26.04 E12.8 | D35L2.SS 192.41,10.16 187.32,10.16 186.06,11.43 C11.2 185.42,10.79 174.62,10.79 | 174.62,10.79 173.35,12.06 E11.5 | 174.62,10.79 167,10.79 165.74,12.06 E11.8 | 186.06,57.15 203.84,57.15 205.1,55.88 D35L1.A | D36L2.E 137.79,50.8 139.06,49.53 141.6,49.53 142.88,48.26 147.96,48.26 D36L1.H
  Bottom 0.508: v110.49,12.7 136.53,12.7 D36L2.PP | 182.88,95.89 182.88,95.25 E17.16
INIT  (via drill 0.61)
  Top 0.254: v147.32,67.94 147.32,64.77 E18.12 147.32,62.23 147.32,3.17 170.81,3.17 171.45,3.81 171.45,6.99 180.97,6.99 181.61,6.35 181.61,3.17 205.74,3.17 209.55,6.99 215.26,6.99 E1.8 | v167.64,67.94 170.18,70.48 170.18,71.12 E15.5 170.81,71.75 172.09,71.75 E15.4 | IC8.7 19.68,59.05 18.41,59.05 IC8.6 17.78,60.96 19.05,62.23 19.05,68.58 38.1,87.63 41.91,87.63 41.91,92.71 46.35,97.16 49.53,97.16 49.53,98.42 59.05,107.95 97.79,107.95 | 111.12,97.16 114.3,100.33 E26.5 | 111.12,97.16 109.22,95.25 E26.8 | 97.79,107.95 103.5,107.95 103.5,104.78 111.12,97.16 | v109.86,67.94 104.78,73.03 104.78,85.72 97.79,92.71 97.79,107.95
  Bottom 0.254: v167.64,67.94 v147.32,67.94 114.94,67.94 114.3,68.58 110.49,68.58 v109.86,67.94 | E26.2 121.28,100.97 120.02,99.69 116.2,99.69 114.94,100.97 E26.5
INIT1\  (via drill 0.61)
  Top 0.254: v170.81,7.62 170.81,8.26 167.64,11.43 E11.7 | v222.25,11.43 222.25,25.4 223.52,26.67 E2.4
  Bottom 0.254: v170.81,7.62 191.13,7.62 192.41,6.35 212.09,6.35 217.17,11.43 v222.25,11.43
INIT4\  (via drill 0.61)
  Top 0.254: v210.19,26.04 209.55,26.67 209.55,56.52 207.01,59.05 203.2,59.05 v203.2,41.91
  Bottom 0.254: v210.19,26.04 224.16,26.04 225.43,27.3 E2.3 | v203.2,41.91 166.37,41.91 163.83,39.37 163.83,36.2 165.74,36.2 167,37.47 E13.7
INIT\  (via drill 0.61)
  Top 0.254: 232.41,50.8 232.41,44.45 229.87,41.91 229.87,22.86 228.6,21.59 E2.13 | 232.41,50.8 233.68,52.07 E4.1 | 232.41,50.8 232.41,83.82 233.68,85.09 E6.1 | 125.73,38.1 125.73,27.94 127,26.67 E21.1 | 125.73,38.1 127,39.37 E22.1 | 125.73,38.1 125.73,53.34 127,54.61 E23.1 127,57.15 v127,61.59 | v107.95,67.31 111.12,64.14 E24.9 | v166.37,56.52 166.37,69.85 167.64,71.12 E15.6 167,73.03 165.1,74.93 166.37,76.2 166.37,80.01 v168.28,81.92
  Bottom 0.254: v127,61.59 113.67,61.59 112.39,62.87 E24.9 | v107.95,67.31 100.33,67.31 99.06,68.58 E30.1 | v166.37,56.52 165.1,55.24 153.67,55.24 151.76,57.15 142.88,57.15 140.34,54.61 131.44,54.61 130.18,55.88 127.64,55.88 E23.1 | v168.28,81.92 229.24,81.92 233.04,85.72 E6.1
INT_RQ\  (via drill 0.61)
  Top 0.254: v199.39,4.45 199.39,76.2 198.12,77.47 IC10.5 | v123.19,5.08 v114.3,13.97
  Bottom 0.254: v199.39,4.45 198.12,3.17 146.05,3.17 144.15,5.08 v123.19,5.08 | v114.3,13.97 64.14,13.97 61.59,16.51 60.33,16.51 59.69,17.14 59.69,29.21 | 59.69,29.21 59.69,30.48 60.33,30.48 D34L2.Z | 59.69,29.21 69.22,29.21 70.48,30.48 D34L1.Z
INTR4\  (via drill 0.61)
  Top 0.254: v129.54,73.66 132.72,70.48 v132.72,7.62 | v161.29,5.71 166.37,10.79 166.37,27.94 165.1,29.21 E13.9
  Bottom 0.254: v129.54,73.66 97.79,73.66 94.61,70.48 E30.3 | v132.72,7.62 134.62,5.71 v161.29,5.71
IOS\  (via drill 0.61)
  Top 0.254: v200.66,91.44 200.66,87.63 IC10.3 | v141.6,108.58 135.25,102.23 v135.25,36.83 | v77.47,29.84 71.75,35.56 D34L1.V
  Bottom 0.254: v200.66,91.44 201.29,92.08 209.55,92.08 212.09,94.61 212.09,107.95 142.24,107.95 v141.6,108.58 | v135.25,36.83 127,28.57 78.74,28.57 v77.47,29.84 | D34L2.V 61.59,35.56 62.87,34.29 69.22,34.29 70.48,35.56 D34L1.V
LCD1
  Top 0.254: E31.2 97.16,85.72 98.42,85.72 E31.1
  Bottom 0.254: E25.6 111.12,85.72 109.86,84.45 104.14,84.45 102.23,86.36 99.69,86.36 E31.1
LCD1\  (via drill 0.61)
  Top 0.254: E11.14 178.44,4.45 180.34,2.54 224.79,2.54 224.79,17.78 223.52,19.05 E2.11 223.52,21.59 224.79,22.86 224.79,72.39 229.87,77.47 229.87,83.82 228.6,85.09 E6.3 | E24.5 114.3,72.39 113.67,73.03 113.67,76.83 113.03,77.47 113.03,83.82 114.3,85.09 E25.5 114.3,87.63 114.94,88.27 114.94,92.08 115.57,92.71 115.57,103.5 v119.38,107.31 | v193.04,104.78 194.31,103.5 194.31,96.52 195.58,95.25 E10.9
  Bottom 0.254: E10.9 195.58,92.71 198.75,89.53 225.43,89.53 227.97,87 E6.3 | v119.38,107.31 120.65,106.05 144.15,106.05 144.78,106.68 151.76,106.68 153.67,104.78 v193.04,104.78
MAINT  (via drill 0.61)
  Top 0.254: E36.6 35.56,54.61 35.56,49.53 E36.9 35.56,46.99 35.56,41.91 E35.6 35.56,39.37 35.56,34.29 E35.9 36.2,33.66 42.55,40.01 E35.3 | v222.25,106.68 222.25,88.9 223.52,87.63 E6.5 | v90.81,106.05 87.63,102.87 87.63,96.52 86.36,95.25 E32.9 86.36,92.71 81.92,88.27 81.92,69.22 v72.39,59.69
  Bottom 0.254: E36.6 36.2,55.24 37.47,53.98 43.81,53.98 45.09,55.24 E36.2 46.35,56.52 49.53,59.69 v72.39,59.69 | v222.25,106.68 216.53,112.39 116.84,112.39 109.86,105.41 91.44,105.41 v90.81,106.05
MAINT\  (via drill 0.61)
  Top 0.254: E6.10 223.52,80.01 223.52,82.55 220.98,85.09 E6.6 220.98,87.63 219.71,88.9 219.71,95.25 214.63,100.33 214.63,103.5 205.1,103.5 203.84,102.23 E10.3 | E31.9 87,78.11 88.27,78.11 E31.10 88.9,80.01 88.9,85.09 E31.5 | v120.65,76.83 120.65,66.04 121.92,64.77 E24.13
  Bottom 0.254: 132.08,76.83 140.34,76.83 141.6,78.11 E19.10 | 132.08,76.83 v120.65,76.83 103.5,76.83 102.87,76.2 91.44,76.2 89.53,78.11 E31.10 | 142.88,88.27 144.15,87 E19.4 | 142.88,88.27 128.27,88.27 125.73,85.72 125.73,81.28 127.64,81.28 132.08,76.83 | 142.88,88.27 219.07,88.27 220.34,87 E6.6
MSB8  (via drill 0.61)
  Top 0.254: v95.25,20.95 95.25,30.48 93.98,31.75 IC1.6 | v198.12,67.94 198.12,69.85 E8.5 | v125.73,66.67 125.73,60.96 124.46,59.69 124.46,57.15 E23.2 | E21.12 116.84,19.05 115.57,20.32 115.57,34.29 116.2,34.92 117.47,34.92 118.11,34.29 118.11,31.75 118.75,31.11 120.65,31.11 120.65,53.34 121.92,54.61 E23.3
  Bottom 0.254: v95.25,20.95 95.89,20.32 99.06,20.32 99.69,19.68 100.33,19.68 100.97,20.32 114.3,20.32 116.2,18.41 E21.12 | E23.3 122.56,55.24 123.83,55.24 E23.2 | v198.12,67.94 197.49,68.58 169.54,68.58 167.64,66.67 167,66.67 166.37,67.31 147.96,67.31 147.32,66.67 v125.73,66.67
MSB12  (via drill 0.61)
  Top 0.254: v199.39,104.14 199.39,84.45 200.66,84.45 204.47,80.64 204.47,73.66 205.74,72.39 E8.2 | v139.06,107.31 133.99,102.23 v133.99,64.14 | v125.73,59.69 125.73,54.61 125.09,53.98 123.19,53.98 123.19,57.15 122.56,57.78 118.11,57.78 118.11,50.8 116.84,49.53 E23.12
  Bottom 0.254: IC6.1 87,55.24 89.53,52.7 112.39,52.7 116.2,48.9 E23.12 | v199.39,104.14 197.49,106.05 178.44,106.05 177.8,105.41 154.31,105.41 152.4,107.31 v139.06,107.31 | v133.99,64.14 129.54,59.69 v125.73,59.69
MYDEV\
  Top 0.254: 173.99,22.86 173.99,15.24 175.26,13.97 E11.4 | 173.99,22.86 175.26,24.13 E12.4 | 173.99,22.86 173.99,35.56 175.26,36.83 E13.4 175.26,39.37 175.26,43.18 168.28,43.18 IOT.1
N$1
  Top 0.254: E14.9 165.1,49.53 165.1,46.35 76.1
N$2
  Bottom 0.254: IC1.1 99.69,41.27 104.14,45.72 119.38,45.72 121.28,47.62 E23.14
N$3  (via drill 0.61)
  Top 0.254: 83.19,10.16 83.19,17.14 IC3.7 83.82,19.05 83.82,24.13 IC3.2 83.82,26.67 82.55,27.94 82.55,38.1 83.82,39.37 IC2.2 | 83.19,10.16 83.19,6.35 57.78,6.35 48.26,15.88 48.26,29.21 45.72,31.75 E35.13 | v121.92,66.04 121.92,69.85 E24.2 | v99.06,66.04 97.79,64.77 97.79,58.42 96.52,57.15 IC5.2 96.52,54.61 96.52,49.53 IC5.7 96.52,46.99 95.25,45.72 95.25,35.56 96.52,34.29 IC1.7 96.52,31.75 96.52,26.67 IC4.2 96.52,24.13 96.52,19.05 IC4.7 95.89,17.14 95.89,10.16 83.19,10.16
  Bottom 0.254: v99.06,66.04 v121.92,66.04
N$4  (via drill 0.61)
  Top 0.254: v63.5,39.37 67.31,43.18 67.31,64.77 72.39,69.85 72.39,71.75 81.28,80.64 81.28,90.17 83.82,92.71 E32.8
  Bottom 0.254: v63.5,39.37 57.78,39.37 56.52,38.1 45.72,38.1 41.27,33.66 E35.11
N$5
  Top 0.254: E14.15 180.34,49.53 180.34,46.35 70.1
N$6
  Top 0.254: E14.14 177.8,49.53 177.8,46.35 71.1
N$7
  Top 0.254: E14.13 175.26,49.53 175.26,46.35 72.1
N$8
  Top 0.254: E14.12 172.72,49.53 172.72,46.35 73.1
N$9
  Top 0.254: E14.11 170.18,49.53 170.18,46.35 74.1
N$10
  Top 0.254: E14.10 167.64,49.53 167.64,46.35 75.1
N$11
  Bottom 0.254: E14.7 167.64,57.15 167.64,52.7 164.47,52.7 162.56,50.8 162.56,46.35 77.1
N$12  (via drill 0.61)
  Top 0.254: IC2.7 83.82,34.29 85.09,35.56 85.09,43.18 v84.45,43.81 83.82,44.45 83.82,46.99 IC6.7 83.82,49.53 83.82,54.61 IC6.2 | v107.31,69.22 105.41,67.31 105.41,44.45 103.5,42.55 96.52,42.55 96.52,41.91 IC1.2
  Bottom 0.254: v84.45,43.81 93.34,43.81 95.89,41.27 IC1.2 | v107.31,69.22 117.47,69.22 118.75,70.48 E24.3
N$13
  Top 0.254: E38.1 48.26,100.33 48.26,100.97 PAD10.1
N$14
  Top 0.254: E38.2 45.72,100.33 45.72,100.97 PAD11.1
N$15
  Top 0.254: E38.3 43.18,100.33 43.18,100.97 PAD12.1
N$16
  Top 0.254: E38.4 40.64,100.33 40.64,100.97 PAD13.1
N$17
  Top 0.254: E38.5 38.1,100.33 38.1,100.97 PAD14.1
N$18
  Top 0.254: E38.6 35.56,100.33 35.56,100.97 PAD15.1
N$19
  Top 0.254: E38.7 33.02,100.33 33.02,100.97 PAD16.1
N$20
  Top 0.254: E38.8 30.48,100.33 30.48,100.97 PAD17.1
N$21  (via drill 0.61)
  Top 0.254: v227.33,55.24 227.33,68.58 228.6,69.85 E5.3
  Bottom 0.254: v227.33,55.24 225.43,55.24 224.16,53.98 E4.5
N$22  (via drill 0.61)
  Top 0.254: v114.3,67.31 114.3,64.77 E24.10 | v146.05,65.41 146.05,91.44 144.78,92.71 E20.11
  Bottom 0.254: v114.3,67.31 123.83,67.31 125.73,65.41 126.36,66.04 146.05,66.04 | 146.05,66.04 163.83,66.04 164.47,66.67 165.74,66.67 167,65.41 E15.9 | 146.05,66.04 v146.05,65.41
N$23
  Top 0.254: E38.16 48.26,90.17 48.26,89.53 PAD20.1
N$24
  Top 0.254: E38.15 45.72,90.17 45.72,89.53 PAD21.1
N$25
  Top 0.254: E38.14 43.18,90.17 43.18,89.53 PAD22.1
N$26
  Top 0.254: E38.13 40.64,90.17 40.64,89.53 PAD23.1
N$27
  Top 0.254: E38.12 38.1,90.17 38.1,89.53 PAD24.1
N$28
  Top 0.254: E38.11 35.56,90.17 35.56,89.53 PAD25.1
N$29
  Top 0.254: E38.10 33.02,90.17 33.02,89.53 PAD26.1
N$30
  Top 0.254: E38.9 30.48,90.17 30.48,89.53 PAD27.1
N$31  (via drill 0.61)
  Top 0.254: E21.2 123.83,24.77 122.56,24.77 E21.3 121.92,26.67 116.84,31.75 E22.12 | v92.71,31.11 92.71,20.32 93.98,19.05 IC4.6
  Bottom 0.254: v92.71,31.11 114.94,31.11 116.2,32.38 E22.12
N$32  (via drill 0.61)
  Top 0.254: v121.92,59.05 121.92,59.69 119.38,62.23 E24.12
  Bottom 0.254: v121.92,59.05 122.56,58.42 137.16,58.42 140.34,61.59 161.93,61.59 164.47,64.14 E15.8
N$33
  Bottom 0.254: IC6.6 81.92,47.62 83.19,46.35 117.47,46.35 118.75,47.62 E23.13
N$34
  Top 0.254: E40.1 25.4,100.33 25.4,100.97 PAD18.1
N$35
  Bottom 0.254: E5.11 226.69,64.14 233.04,70.48 E5.1
N$36
  Top 0.254: E1.10 220.34,6.99 219.07,6.99 E1.9 218.44,8.89 218.44,13.97 E1.6
  Bottom 0.254: E2.1 231.78,27.94 234.31,27.94 234.95,27.3 234.95,17.14 230.5,17.14 229.87,16.51 229.87,13.34 220.34,13.34 219.07,14.61 E1.6
N$37  (via drill 0.61)
  Top 0.254: E8.13 205.74,64.77 203.2,67.31 203.2,69.85 E8.3 | v175.26,67.31 175.26,71.12 E15.3
  Bottom 0.254: v175.26,67.31 197.49,67.31 199.39,65.41 203.84,65.41 205.1,64.14 E8.13
N$38
  Bottom 0.254: E8.11 201.29,62.87 202.56,62.87 E8.12
N$39
  Top 0.254: E8.9 195.58,64.77 195.58,69.85 E8.6
N$40
  Bottom 0.254: E8.10 197.49,62.87 196.22,61.59 173.99,61.59 172.72,62.87 172.72,63.5 E15.11
N$41
  Top 0.254: E40.2 22.86,100.33 22.86,100.97 PAD19.1
N$42  (via drill 0.61)
  Top 0.254: v189.23,90.17 189.23,68.58 193.04,64.77 E8.8
  Bottom 0.254: IC7.7 66.67,93.34 67.94,92.08 163.19,92.08 164.47,93.34 E17.9 165.74,94.61 167,95.89 170.81,95.89 172.09,94.61 E17.12 173.35,93.34 174.62,92.08 187.32,92.08 v189.23,90.17
N$43
  Top 0.254: E40.3 20.32,100.33 20.32,100.97 PAD28.1
N$44
  Top 0.254: E24.6 111.76,72.39 110.49,73.66 110.49,90.17 107.31,93.34 107.31,96.52 102.23,101.6 99.69,101.6 E32.1
N$45
  Top 0.254: E1.11 223.52,8.89 219.71,12.7 219.71,25.4 218.44,26.67 E2.6
N$46
  Top 0.254: E18.13 150.5,62.87 151.76,61.59 158.75,61.59 158.75,93.98 165.1,100.33 E17.8
N$47
  Top 0.254: E25.10 114.3,80.01 115.57,81.28 115.57,91.44 116.84,92.71 E26.11 117.47,93.34 118.75,93.34 E26.12
N$48
  Top 0.254: E4.10 218.44,46.99 218.44,52.07 E4.7 | E4.3 227.97,52.7 226.69,52.7 E4.4 226.06,54.61 226.06,57.78 R19.2
  Bottom 0.254: E4.7 218.44,54.61 218.44,58.42 225.43,58.42 R19.2
N$49  (via drill 0.61)
  Top 0.254: E14.5 173.35,57.78 174.62,57.78 E14.4 | v191.77,5.71 189.87,7.62 v189.87,43.18
  Bottom 0.254: v191.77,5.71 224.16,5.71 225.43,6.99 E1.12 | v189.87,43.18 188.59,44.45 177.16,44.45 176.53,45.09 176.53,57.15 175.26,57.15 E14.4
N$50
  Top 0.254: E40.4 17.78,100.33 17.78,100.97 PAD29.1
N$51
  Top 0.254: E40.5 15.24,100.33 15.24,100.97 PAD30.1
N$52
  Top 0.254: E40.6 12.7,100.33 12.7,100.97 PAD31.1
N$53
  Top 0.254: E40.7 10.16,100.33 10.16,100.97 PAD32.1
N$54
  Top 0.254: E40.8 7.62,100.33 7.62,100.97 PAD33.1
N$55
  Top 0.254: E40.16 25.4,90.17 25.4,89.53 PAD34.1
N$56
  Top 0.254: E40.15 22.86,90.17 22.86,89.53 PAD35.1
N$57
  Top 0.254: E40.14 20.32,90.17 20.32,89.53 PAD36.1
N$58
  Top 0.254: E40.13 17.78,90.17 17.78,89.53 PAD37.1
N$59
  Top 0.254: E40.12 15.24,90.17 15.24,89.53 PAD38.1
N$60  (via drill 0.61)
  Top 0.254: v81.28,29.84 81.28,31.75 IC2.6 | v121.28,29.84 123.19,31.75 123.19,45.72 124.46,46.99 E23.15
  Bottom 0.254: v81.28,29.84 v121.28,29.84
N$61
  Top 0.254: E40.11 12.7,90.17 12.7,89.53 PAD39.1
N$62  (via drill 0.61)
  Top 0.254: v99.69,20.95 99.69,23.5 99.06,24.13 IC4.1
  Bottom 0.254: v99.69,20.95 116.2,20.95 118.75,18.41 E21.13
N$63
  Bottom 0.254: IC3.1 87,24.77 89.53,22.23 117.47,22.23 121.28,18.41 E21.14
N$64
  Bottom 0.254: IC3.6 81.92,17.14 83.19,15.88 122.56,15.88 123.83,17.14 E21.15
N$65
  Bottom 0.254: IC2.1 87,40.01 89.53,37.47 120.02,37.47 123.83,33.66 E22.15
N$66  (via drill 0.61)
  Top 0.254: v106.68,55.88 113.03,49.53 113.03,46.99 118.11,41.91 118.11,35.56 119.38,34.29 E22.13
  Bottom 0.254: v106.68,55.88 99.69,55.88 IC5.1
N$67  (via drill 0.61)
  Top 0.254: v92.71,36.2 92.71,45.72 93.98,46.99 IC5.6
  Bottom 0.254: v92.71,36.2 93.34,35.56 119.38,35.56 121.28,33.66 E22.14
N$68
  Top 0.254: E40.10 10.16,90.17 10.16,89.53 PAD40.1
N$69
  Top 0.254: E40.9 7.62,90.17 7.62,89.53 PAD41.1
N$70
  Top 0.254: E39.1 233.68,102.87 233.68,103.5 PAD42.1
N$71
  Top 0.254: E39.2 231.14,102.87 231.14,103.5 PAD43.1
N$72
  Top 0.254: E39.3 228.6,102.87 228.6,103.5 PAD44.1
N$73
  Top 0.254: E39.4 226.06,102.87 226.06,103.5 PAD45.1
N$74
  Top 0.254: E39.5 223.52,102.87 223.52,103.5 PAD46.1
N$75
  Top 0.254: E39.6 220.98,102.87 220.98,103.5 PAD47.1
N$76
  Top 0.254: E39.7 218.44,102.87 218.44,103.5 PAD48.1
N$77
  Top 0.254: E39.8 215.9,102.87 215.9,103.5 PAD49.1
N$78
  Top 0.254: E39.16 233.68,92.71 233.68,92.08 PAD50.1
N$79
  Top 0.254: E39.15 231.14,92.71 231.14,92.08 PAD51.1
N$80
  Top 0.254: E39.14 228.6,92.71 228.6,92.08 PAD52.1
N$81
  Top 0.254: E39.13 226.06,92.71 226.06,92.08 PAD53.1
N$82
  Top 0.254: E39.12 223.52,92.71 223.52,92.08 PAD54.1
N$83
  Top 0.254: E39.11 220.98,92.71 220.98,92.08 PAD55.1
N$84
  Top 0.254: E39.10 218.44,92.71 218.44,92.08 PAD56.1
N$85
  Top 0.254: E39.9 215.9,92.71 215.9,92.08 PAD57.1
N$86  (via drill 0.61)
  Top 0.254: v90.17,11.43 90.17,39.37 85.09,44.45 85.09,64.77 88.9,68.58 E30.5 | v194.31,8.89 194.31,77.47 197.49,80.64 203.2,80.64 203.2,80.01 IC10.7
  Bottom 0.254: v90.17,11.43 92.71,8.89 140.34,8.89 142.88,6.35 160.66,6.35 163.19,8.89 v194.31,8.89
N$87
  Top 0.254: E32.12 93.98,95.25 91.44,97.79 91.44,100.33 E32.4
  Bottom 0.254: E32.5 89.53,100.97 90.81,100.97 E32.4
N$88
  Bottom 0.254: E20.6 140.34,100.97 141.6,99.69 147.96,99.69 149.22,100.97 E20.2
N$89  (via drill 0.61)
  Top 0.254: IC10.1 205.1,85.72 203.84,85.72 IC10.2 203.2,87.63 201.93,88.9 201.93,103.5 v198.75,106.68 | v177.8,106.68 147.96,106.68 147.96,103.5 147.32,102.87 E20.3
  Bottom 0.254: v177.8,106.68 v198.75,106.68
N$92  (via drill 0.61)
  Top 0.254: v138.43,74.3 138.43,66.04 139.7,64.77 E18.9 | v166.37,74.93 169.54,78.11 E16.11
  Bottom 0.254: v138.43,74.3 139.06,74.93 v166.37,74.93
N$93
  Top 0.254: E18.6 139.7,72.39 139.7,76.2 138.43,77.47 138.43,97.79 140.97,100.33 140.97,102.87 146.05,107.95 179.07,107.95 179.07,81.28 177.8,80.01 E16.14
N$94  (via drill 0.61)
  Top 0.254: IC9.3 63.5,77.47 66.04,80.01 66.04,80.64 R18.1 | v92.71,71.75 92.71,64.77 91.44,63.5 E30.11
  Bottom 0.254: v92.71,71.75 91.44,73.03 64.14,73.03 63.5,73.66 63.5,74.93 IC9.3
N$95
  Bottom 0.254: IC9.2 66.67,76.83 67.94,78.11 83.19,78.11 E31.8
N$96  (via drill 0.61)
  Top 0.254: v148.59,76.83 148.59,73.66 147.32,72.39 E18.3
  Bottom 0.254: v148.59,76.83 160.02,76.83 166.37,83.19 179.71,83.19 182.25,85.72 E16.1
N$98  (via drill 0.61)
  Top 0.254: v71.12,84.45 71.12,80.01 68.58,77.47 IC9.1
  Bottom 0.254: v71.12,84.45 84.45,84.45 85.72,85.72 E31.6
N$99  (via drill 0.61)
  Top 0.254: v97.16,65.41 97.16,64.14 96.52,63.5 E30.13
  Bottom 0.254: v97.16,65.41 97.79,64.77 109.22,64.77 E24.8
N$100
